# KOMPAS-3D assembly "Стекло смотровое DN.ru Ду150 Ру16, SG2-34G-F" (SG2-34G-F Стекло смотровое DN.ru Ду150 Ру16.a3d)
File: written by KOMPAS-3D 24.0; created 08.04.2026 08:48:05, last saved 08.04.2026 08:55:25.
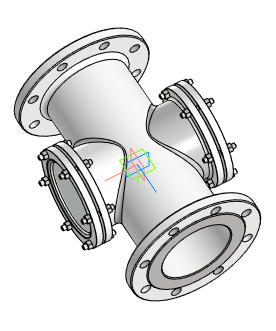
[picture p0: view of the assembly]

Document properties: Автор: Main; Полное имя файла: D:\DN.ru Аутсерс\Стекло смотровое DN.ru\Исходники\Стекло смотровое DN.ru SG2-34G-F тип В ГОСТ 21836-2021 Ду150 Ру16, углеродистая сталь, фланцевое\SG2-34G-F Стекло смотровое DN.ru Ду150 Ру16.a3d

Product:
- Component [detail]: Деталь  | qty 1  | pos. 1  | Масса: 43.197809; Автор: Main; additional columns: Типовые; source file: ДетальДеталь.m3d
- Component [detail]: Стекло  | qty 2  | pos. 2  | Масса: 1.895451; Автор: Main; source file: СтеклоСтекло.m3d
- Component [detail]: ANSI B18.2.4.2M - M10x1,5 - 16  | designation ANSI B18.2.4.2M - M10x1,5  | qty 24  | pos. 3  | Масса: 0.012122; Комментарий: Типы метрических   шестигранных гаек   2; Автор: Main; additional columns: Сталь, мягкая; source file: ANSI B18.2.4.2M - M10x1,5ANSI B18.2.4.2M - M10x1,5 - 16.m3d
- Part/product: Стекло смотровое DN.ru Ду150 Ру16  | designation SG2-34G-F
    Масса: 42
    Раздел спецификации: Прочие изделия
    Примечание: D500-00089

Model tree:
1. Массив по концентрической сетке:1  (labels: Грань.Твердое тело1; Грань.Solid1; Ребро.Твердое тело1; Ребро.Solid1)  (6 pattern instances)
     Шаг 2 = 360

Expressions: SG2-34G-F
Referenced files in D:\DN.ru Аутсерс\Стекло смотровое DN.ru\Исходники\Стекло смотровое DN.ru SG2-34G-F тип В ГОСТ 21836-2021 Ду150 Ру16, углеродистая сталь, фланцевое\: ДетальДеталь.m3d, СтеклоСтекло.m3d, ANSI B18.2.4.2M - M10x1,5ANSI B18.2.4.2M - M10x1,5 - 16.m3d
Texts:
  Стекло Стекло (1)
  Стекло Стекло (2)
  ANSI B18.2.4.2M - M10x1,5 ANSI B18.2.4.2M - M10x1,5 - 16 (1)
  ANSI B18.2.4.2M - M10x1,5 ANSI B18.2.4.2M - M10x1,5 - 16 (2)
  ANSI B18.2.4.2M - M10x1,5 ANSI B18.2.4.2M - M10x1,5 - 16 (3)
  ANSI B18.2.4.2M - M10x1,5 ANSI B18.2.4.2M - M10x1,5 - 16 (4)
  ANSI B18.2.4.2M - M10x1,5 ANSI B18.2.4.2M - M10x1,5 - 16 (5)
  ANSI B18.2.4.2M - M10x1,5 ANSI B18.2.4.2M - M10x1,5 - 16 (6)
  ANSI B18.2.4.2M - M10x1,5 ANSI B18.2.4.2M - M10x1,5 - 16 (7)
  ANSI B18.2.4.2M - M10x1,5 ANSI B18.2.4.2M - M10x1,5 - 16 (8)
  ANSI B18.2.4.2M - M10x1,5 ANSI B18.2.4.2M - M10x1,5 - 16 (9)
  ANSI B18.2.4.2M - M10x1,5 ANSI B18.2.4.2M - M10x1,5 - 16 (10)
  ANSI B18.2.4.2M - M10x1,5 ANSI B18.2.4.2M - M10x1,5 - 16 (11)
  ANSI B18.2.4.2M - M10x1,5 ANSI B18.2.4.2M - M10x1,5 - 16 (12)
  ANSI B18.2.4.2M - M10x1,5 ANSI B18.2.4.2M - M10x1,5 - 16 (13)
  ANSI B18.2.4.2M - M10x1,5 ANSI B18.2.4.2M - M10x1,5 - 16 (14)
  ANSI B18.2.4.2M - M10x1,5 ANSI B18.2.4.2M - M10x1,5 - 16 (15)
  ANSI B18.2.4.2M - M10x1,5 ANSI B18.2.4.2M - M10x1,5 - 16 (16)
  ANSI B18.2.4.2M - M10x1,5 ANSI B18.2.4.2M - M10x1,5 - 16 (17)
  ANSI B18.2.4.2M - M10x1,5 ANSI B18.2.4.2M - M10x1,5 - 16 (18)
  ANSI B18.2.4.2M - M10x1,5 ANSI B18.2.4.2M - M10x1,5 - 16 (19)
  ANSI B18.2.4.2M - M10x1,5 ANSI B18.2.4.2M - M10x1,5 - 16 (20)
  ANSI B18.2.4.2M - M10x1,5 ANSI B18.2.4.2M - M10x1,5 - 16 (21)
  ANSI B18.2.4.2M - M10x1,5 ANSI B18.2.4.2M - M10x1,5 - 16 (22)
  ANSI B18.2.4.2M - M10x1,5 ANSI B18.2.4.2M - M10x1,5 - 16 (23)
  ANSI B18.2.4.2M - M10x1,5 ANSI B18.2.4.2M - M10x1,5 - 16 (24)
  Ось Z.Начало координат
  Ось X.Начало координат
